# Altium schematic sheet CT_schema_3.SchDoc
size 322 x 302 mm
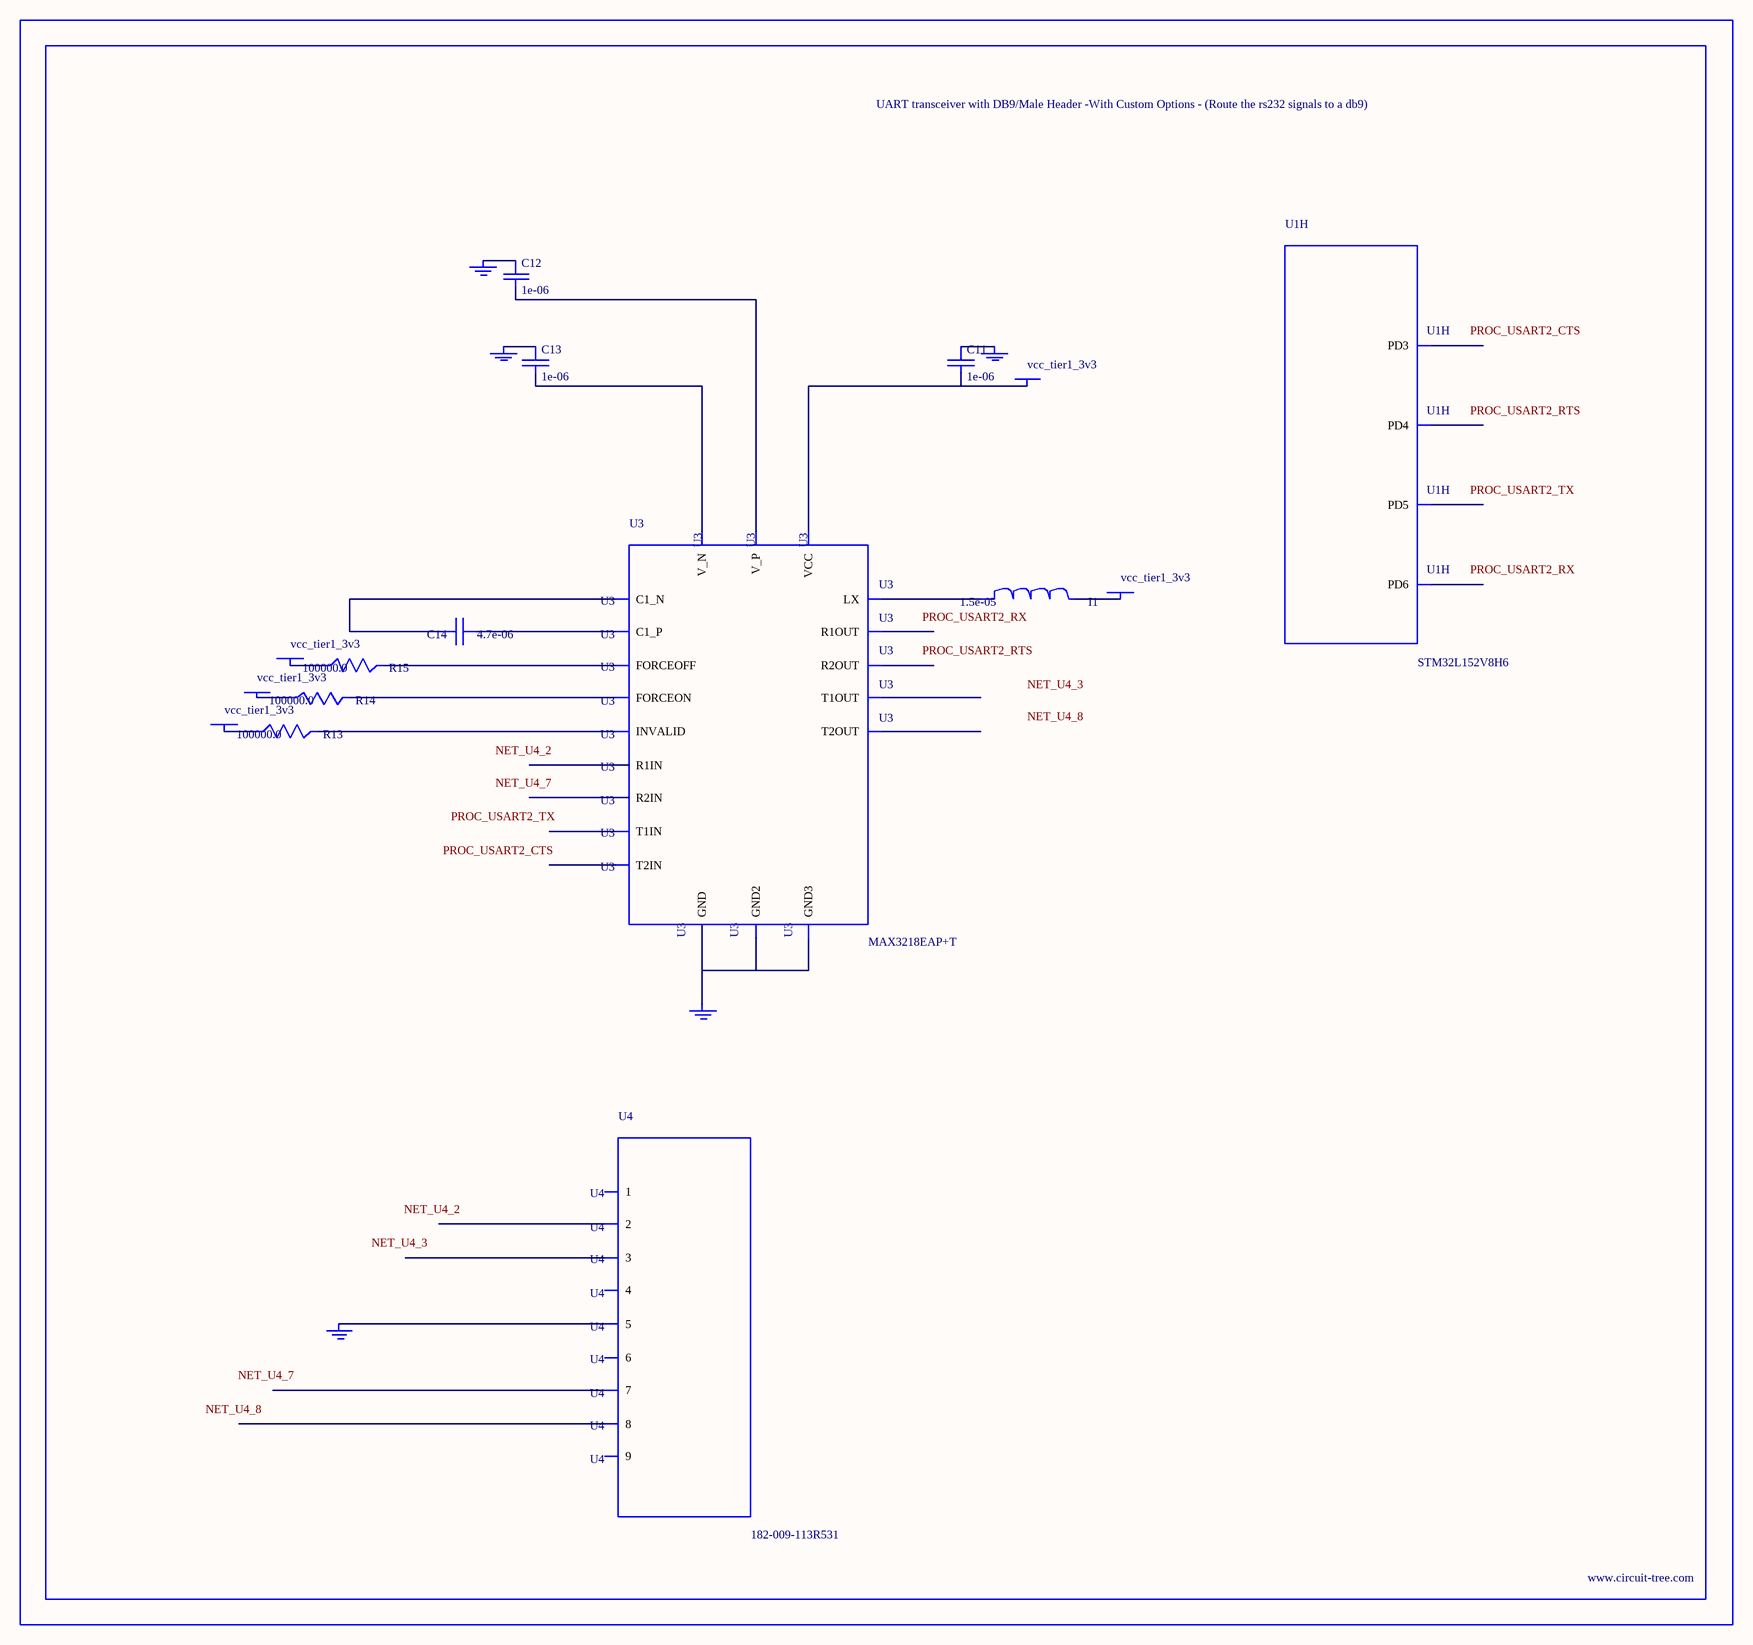
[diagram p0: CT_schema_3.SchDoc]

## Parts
BORDER2  (no value)
C11  1e-06  [C0603]
C12  1e-06  [C0603]
C13  1e-06  [C0603]
C14  4.7e-06  [C0805]
GND_INSTANCE_2_0  (no value)
GND_INSTANCE_2_1  (no value)
GND_INSTANCE_2_2  (no value)
GND_INSTANCE_2_3  (no value)
GND_INSTANCE_2_4  (no value)
I1  1.5e-05  [L1210]
POWER_INSTANCE_2_0  vcc_tier1_3v3
POWER_INSTANCE_2_1  vcc_tier1_3v3
POWER_INSTANCE_2_2  vcc_tier1_3v3
POWER_INSTANCE_2_3  vcc_tier1_3v3
POWER_INSTANCE_2_4  vcc_tier1_3v3
R13  100000.0  [R0603]
R14  100000.0  [R0603]
R15  100000.0  [R0603]
U1  STM32L152V8H6  [UFBGA100]  (part H of 10)
U3  MAX3218EAP+T  [SSOP-20]
U4  182-009-113R531  [182-009-MALE]

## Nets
NetC11_1: C11.1 GND_INSTANCE_2_0.0(GND)
NetC11_2: C11.2 POWER_INSTANCE_2_4.0(PWR) U3.6(VCC)
NetC12_1: C12.1 GND_INSTANCE_2_2.0(GND)
NetC12_2: C12.2 U3.19(V_P)
NetC13_1: C13.1 GND_INSTANCE_2_1.0(GND)
NetC13_2: C13.2 U3.15(V_N)
NetC14_1: C14.1 U3.18(C1_P)
NetC14_2: C14.2 U3.16(C1_N)
NetGND_INSTANCE_2_3_0: GND_INSTANCE_2_3.0(GND) U3.5(GND) U3.17(GND2) U3.20(GND3)
NetGND_INSTANCE_2_4_0: GND_INSTANCE_2_4.0(GND) U4.5
NetI1_1: I1.1 U3.1(LX)
NetI1_2: I1.2 POWER_INSTANCE_2_0.0(PWR)
NetPOWER_INSTANCE_2_1_0: POWER_INSTANCE_2_1.0(PWR) R13.1
NetPOWER_INSTANCE_2_2_0: POWER_INSTANCE_2_2.0(PWR) R14.1
NetPOWER_INSTANCE_2_3_0: POWER_INSTANCE_2_3.0(PWR) R15.1
NetR13_2: R13.2 U3.2(INVALID)
NetR14_2: R14.2 U3.3(FORCEON)
NetR15_2: R15.2 U3.4(FORCEOFF)

Not connected (* = marked no-connect by the designer): U1 A6(PD5) B6(PD6) B7(PD4) B8(PD3); U3 7(T1IN) 8(T2IN) 9(R1OUT) 10(R2OUT) 11(R2IN) 12(R1IN) 13(T2OUT) 14(T1OUT); U4 1 2 3 4 6 7 8 9

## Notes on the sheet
- Labels drawn without touching a wire or pin: NET_U4_2, NET_U4_3, NET_U4_7, NET_U4_8, PROC_USART2_CTS, PROC_USART2_RTS, PROC_USART2_RX, PROC_USART2_TX

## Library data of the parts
BORDER2 = BORDER_PAGE2
C11-C13 = C0603C105K3RACTU
C14 = C0805C475K4RACTU
GND_INSTANCE_2_0-GND_INSTANCE_2_4 = GND
I1 = L1210R150MDWIT
POWER_INSTANCE_2_0-POWER_INSTANCE_2_4 = PWR
R13-R15 = RC0603JR-07100KL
